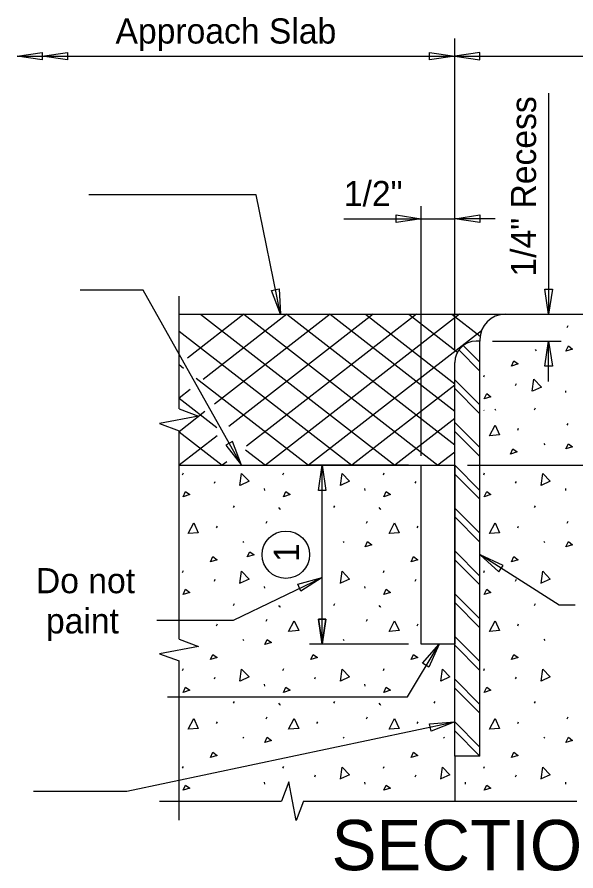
# Model space of a CAD drawing. Extents: x 2799.7 to 2896, y 515.2 to 573.9.
# Drawn here: x 2834.1 to 2841.51, y 530.53 to 541.84 of the extents above; entities that cross this region are included whole.
import ezdxf

# ---------------------------------------------------------------- set-up
doc = ezdxf.new("R2010")
doc.units = 0
for name, color, linetype in [('BR_AUTO DIMENSION', 7, 'Continuous'), ('BR_CONCRETE', 7, 'Continuous'), ('BR_DETAILS', 7, 'Continuous'), ('BR_STRUCTURAL STEEL', 7, 'Continuous'), ('BR_TABLE LINES', 7, 'Continuous'), ('BR_TEXT', 7, 'Continuous')]:
    doc.layers.add(name, color=color, linetype=linetype)

# ---------------------------------------------------------------- blocks, each defined once
blk = doc.blocks.new('B')
at = {"layer": 'BR_AUTO DIMENSION'}
blk.add_lwpolyline([(-0.2, 0.03), (0, 0), (-0.2, -0.03)], close=True, dxfattribs=at)
blk = doc.blocks.new('ARROW')
at = {"layer": 'BR_AUTO DIMENSION', "xscale": 0.625, "yscale": 0.625}
blk.add_blockref('B', (0, 0), dxfattribs=at)
blk = doc.blocks.new('DAH')
at = {"layer": 'BR_AUTO DIMENSION'}
for p in [(-0.1248, 0), (0, 0)]:
    blk.add_blockref('ARROW', p, dxfattribs=at)

msp = doc.modelspace()

# ---------------------------------------------------------------- linework, layer by layer
at = {"layer": 'BR_AUTO DIMENSION'}
for p, q in [((2839.901, 537.568), (2839.901, 541.559)), ((2834.103, 541.324), (2845.404, 541.324)), ((2841.144, 540.834), (2841.144, 537.904)), ((2837.269, 539.488), (2835.055, 539.488)), ((2837.591, 537.904), (2837.269, 539.488)), ((2839.456, 536.071), (2839.456, 539.337)), ((2839.456, 536.027), (2839.456, 539.314)), ((2839.901, 537.432), (2839.901, 539.337)), ((2838.431, 539.171), (2839.456, 539.171)), ((2838.923, 539.171), (2839.456, 539.171)), ((2839.456, 539.171), (2839.901, 539.171)), ((2840.434, 539.171), (2839.901, 539.171)), ((2835.774, 538.223), (2834.937, 538.223)), ((2837.077, 535.904), (2835.774, 538.223)), ((2840.734, 537.904), (2841.31, 537.904)), ((2840.401, 537.55), (2841.31, 537.55)), ((2841.144, 537.016), (2841.144, 537.55)), ((2839.289, 535.904), (2837.978, 535.904)), ((2838.144, 533.534), (2838.144, 535.904)), ((2840.067, 535.904), (2845.988, 535.904)), ((2841.282, 534.05), (2840.235, 534.719)), ((2836.968, 533.852), (2838.144, 534.418)), ((2841.496, 534.05), (2841.282, 534.05)), ((2835.956, 533.852), (2836.968, 533.852)), ((2839.289, 533.534), (2837.978, 533.534)), ((2839.273, 532.836), (2839.695, 533.536)), ((2836.096, 532.836), (2839.273, 532.836)), ((2835.556, 531.588), (2839.901, 532.503)), ((2834.322, 531.588), (2835.556, 531.588))]:
    msp.add_line(p, q, dxfattribs=at)
for points in [[(2839.567, 541.374), (2839.901, 541.324), (2839.567, 541.274)], [(2840.234, 541.374), (2839.901, 541.324), (2840.234, 541.274)], [(2839.123, 539.221), (2839.456, 539.171), (2839.123, 539.121)], [(2840.234, 539.121), (2839.901, 539.171), (2840.234, 539.221)], [(2837.573, 538.241), (2837.591, 537.904), (2837.475, 538.221)], [(2841.194, 538.238), (2841.144, 537.904), (2841.094, 538.238)], [(2841.094, 537.216), (2841.144, 537.55), (2841.194, 537.216)], [(2836.87, 536.17), (2837.077, 535.904), (2836.958, 536.219)], [(2838.094, 535.571), (2838.144, 535.904), (2838.194, 535.571)], [(2838.094, 535.571), (2838.144, 535.904), (2838.194, 535.571)], [(2840.54, 534.576), (2840.235, 534.719), (2840.485, 534.492)], [(2837.82, 534.327), (2838.144, 534.418), (2837.861, 534.236)], [(2838.094, 533.867), (2838.144, 533.534), (2838.194, 533.867)], [(2838.194, 533.867), (2838.144, 533.534), (2838.094, 533.867)], [(2839.473, 533.283), (2839.695, 533.536), (2839.557, 533.229)], [(2839.564, 532.48), (2839.901, 532.503), (2839.586, 532.382)]]:
    msp.add_lwpolyline(points, close=True, dxfattribs=at)
msp.add_circle((2837.663, 534.719), 0.314, dxfattribs=at)
at = {"layer": 'BR_CONCRETE'}
for p, q in [((2840.567, 537.904), (2844.821, 537.904)), ((2840.234, 537.571), (2840.234, 537.55)), ((2836.249, 535.904), (2839.456, 535.904)), ((2839.901, 532.052), (2839.901, 531.454))]:
    msp.add_line(p, q, dxfattribs=at)
msp.add_arc((2840.567, 537.571), 0.333, 90, 180, dxfattribs=at)
at = {"layer": 'BR_DETAILS'}
for p, q in [((2841.391, 537.73), (2841.402, 537.755)), ((2840.967, 537.436), (2840.978, 537.42)), ((2840.284, 537.075), (2840.295, 537.1)), ((2840.706, 536.962), (2840.717, 536.987)), ((2841.366, 536.892), (2841.368, 536.867)), ((2840.285, 536.635), (2840.288, 536.63)), ((2840.43, 536.65), (2840.441, 536.633)), ((2840.958, 536.64), (2840.969, 536.665)), ((2841.391, 536.434), (2841.402, 536.459)), ((2840.734, 536.37), (2840.745, 536.395)), ((2841.08, 536.193), (2841.092, 536.176)), ((2836.296, 535.779), (2836.307, 535.804)), ((2837.625, 535.779), (2837.636, 535.804)), ((2838.955, 535.779), (2838.966, 535.804)), ((2840.284, 535.779), (2840.295, 535.804)), ((2836.718, 535.665), (2836.729, 535.69)), ((2839.376, 535.665), (2839.388, 535.69)), ((2840.706, 535.665), (2840.717, 535.69)), ((2837.378, 535.596), (2837.38, 535.571)), ((2838.707, 535.596), (2838.71, 535.571)), ((2841.366, 535.596), (2841.368, 535.571)), ((2836.97, 535.343), (2836.981, 535.368)), ((2837.567, 535.343), (2837.578, 535.327)), ((2837.578, 535.337), (2837.589, 535.32)), ((2838.3, 535.343), (2838.311, 535.368)), ((2838.896, 535.343), (2838.907, 535.327)), ((2838.907, 535.337), (2838.919, 535.32)), ((2840.958, 535.343), (2840.969, 535.368)), ((2837.403, 535.138), (2837.414, 535.163)), ((2838.733, 535.138), (2838.744, 535.163)), ((2841.391, 535.138), (2841.402, 535.163)), ((2836.745, 535.074), (2836.757, 535.099)), ((2839.404, 535.074), (2839.415, 535.099)), ((2840.734, 535.074), (2840.745, 535.099)), ((2837.092, 534.896), (2837.103, 534.88)), ((2838.422, 534.896), (2838.433, 534.88)), ((2841.08, 534.896), (2841.092, 534.88)), ((2836.296, 534.483), (2836.307, 534.508)), ((2838.955, 534.483), (2838.966, 534.508)), ((2840.284, 534.483), (2840.295, 534.508)), ((2836.718, 534.369), (2836.729, 534.394)), ((2838.047, 534.369), (2838.058, 534.394)), ((2839.376, 534.369), (2839.388, 534.394)), ((2840.706, 534.369), (2840.717, 534.394)), ((2837.378, 534.299), (2837.38, 534.274)), ((2838.707, 534.299), (2838.71, 534.274)), ((2836.97, 534.047), (2836.981, 534.072)), ((2837.567, 534.047), (2837.578, 534.03)), ((2837.578, 534.041), (2837.589, 534.024)), ((2838.3, 534.047), (2838.311, 534.072)), ((2838.896, 534.047), (2838.907, 534.03)), ((2838.907, 534.041), (2838.919, 534.024)), ((2840.958, 534.047), (2840.969, 534.072)), ((2837.403, 533.841), (2837.414, 533.866)), ((2838.733, 533.841), (2838.744, 533.866)), ((2836.745, 533.777), (2836.757, 533.802)), ((2839.404, 533.777), (2839.415, 533.802)), ((2840.734, 533.777), (2840.745, 533.802)), ((2837.092, 533.6), (2837.103, 533.583)), ((2838.422, 533.6), (2838.433, 533.583)), ((2841.08, 533.6), (2841.092, 533.583)), ((2836.296, 533.186), (2836.307, 533.211)), ((2837.625, 533.186), (2837.636, 533.211)), ((2838.955, 533.186), (2838.966, 533.211)), ((2840.284, 533.186), (2840.295, 533.211)), ((2836.718, 533.073), (2836.729, 533.098)), ((2838.047, 533.073), (2838.058, 533.098)), ((2840.706, 533.073), (2840.717, 533.098)), ((2837.378, 533.003), (2837.38, 532.978)), ((2838.707, 533.003), (2838.71, 532.978)), ((2836.97, 532.751), (2836.981, 532.776)), ((2837.567, 532.751), (2837.578, 532.734)), ((2837.578, 532.744), (2837.589, 532.728)), ((2838.3, 532.751), (2838.311, 532.776)), ((2838.896, 532.751), (2838.907, 532.734)), ((2838.907, 532.744), (2838.919, 532.728)), ((2839.629, 532.751), (2839.64, 532.776)), ((2840.958, 532.751), (2840.969, 532.776)), ((2837.403, 532.545), (2837.414, 532.57)), ((2838.733, 532.545), (2838.744, 532.57)), ((2841.391, 532.545), (2841.402, 532.57)), ((2836.745, 532.481), (2836.757, 532.506)), ((2838.075, 532.481), (2838.086, 532.506)), ((2839.404, 532.481), (2839.415, 532.506)), ((2840.734, 532.481), (2840.745, 532.506)), ((2837.092, 532.303), (2837.103, 532.287)), ((2838.422, 532.303), (2838.433, 532.287)), ((2839.751, 532.303), (2839.762, 532.287)), ((2841.08, 532.303), (2841.092, 532.287)), ((2836.296, 531.89), (2836.307, 531.915)), ((2837.625, 531.89), (2837.636, 531.915)), ((2838.955, 531.89), (2838.966, 531.915)), ((2840.284, 531.89), (2840.295, 531.915)), ((2838.047, 531.776), (2838.058, 531.801)), ((2839.376, 531.776), (2839.388, 531.801)), ((2840.706, 531.776), (2840.717, 531.801)), ((2837.378, 531.706), (2837.38, 531.681)), ((2838.707, 531.706), (2838.71, 531.681)), ((2840.036, 531.706), (2840.039, 531.681)), ((2841.366, 531.706), (2841.368, 531.681)), ((2835.991, 531.454), (2837.607, 531.454)), ((2837.897, 531.454), (2841.515, 531.454))]:
    msp.add_line(p, q, dxfattribs=at)
for points in [[(2836.249, 536.65), (2836.249, 538.143)], [(2841.372, 537.417), (2841.405, 537.486), (2841.461, 537.444), (2841.372, 537.417)], [(2840.651, 537.218), (2840.684, 537.288), (2840.74, 537.246), (2840.651, 537.218)], [(2840.927, 536.885), (2840.949, 537.044), (2841.048, 536.941), (2840.929, 536.886)], [(2840.29, 536.784), (2840.323, 536.853), (2840.378, 536.812), (2840.29, 536.784)], [(2836.249, 536.65), (2836.506, 536.553), (2835.991, 536.457), (2836.249, 536.36)], [(2840.359, 536.295), (2840.434, 536.437), (2840.492, 536.306), (2840.362, 536.295)], [(2836.249, 533.601), (2836.249, 536.36)], [(2841.372, 536.12), (2841.405, 536.19), (2841.461, 536.148), (2841.372, 536.12)], [(2840.637, 536.053), (2840.67, 536.122), (2840.725, 536.081), (2840.637, 536.053)], [(2837.055, 535.637), (2837.077, 535.795), (2837.177, 535.693), (2837.058, 535.637)], [(2838.385, 535.637), (2838.407, 535.795), (2838.506, 535.693), (2838.387, 535.637)], [(2841.043, 535.637), (2841.065, 535.795), (2841.165, 535.693), (2841.046, 535.637)], [(2836.301, 535.488), (2836.335, 535.557), (2836.39, 535.515), (2836.301, 535.488)], [(2837.631, 535.488), (2837.664, 535.557), (2837.72, 535.515), (2837.631, 535.488)], [(2838.96, 535.488), (2838.993, 535.557), (2839.049, 535.515), (2838.96, 535.488)], [(2840.29, 535.488), (2840.323, 535.557), (2840.378, 535.515), (2840.29, 535.488)], [(2836.371, 534.999), (2836.446, 535.14), (2836.504, 535.01), (2836.374, 534.999)], [(2839.03, 534.999), (2839.104, 535.14), (2839.163, 535.01), (2839.032, 534.999)], [(2840.359, 534.999), (2840.434, 535.14), (2840.492, 535.01), (2840.362, 534.999)], [(2838.713, 534.824), (2838.746, 534.893), (2838.802, 534.852), (2838.713, 534.824)], [(2841.372, 534.824), (2841.405, 534.893), (2841.461, 534.852), (2841.372, 534.824)], [(2837.153, 534.69), (2837.187, 534.759), (2837.242, 534.718), (2837.153, 534.69)], [(2836.663, 534.626), (2836.696, 534.695), (2836.752, 534.653), (2836.663, 534.626)], [(2839.321, 534.626), (2839.355, 534.695), (2839.41, 534.653), (2839.321, 534.626)], [(2840.651, 534.626), (2840.684, 534.695), (2840.74, 534.653), (2840.651, 534.626)], [(2837.055, 534.34), (2837.077, 534.499), (2837.177, 534.396), (2837.058, 534.341)], [(2838.385, 534.34), (2838.407, 534.499), (2838.506, 534.396), (2838.387, 534.341)], [(2841.043, 534.34), (2841.065, 534.499), (2841.165, 534.396), (2841.046, 534.341)], [(2836.301, 534.191), (2836.335, 534.261), (2836.39, 534.219), (2836.301, 534.191)], [(2838.96, 534.191), (2838.993, 534.261), (2839.049, 534.219), (2838.96, 534.191)], [(2840.29, 534.191), (2840.323, 534.261), (2840.378, 534.219), (2840.29, 534.191)], [(2837.7, 533.703), (2837.775, 533.844), (2837.833, 533.714), (2837.703, 533.703)], [(2839.03, 533.703), (2839.104, 533.844), (2839.163, 533.714), (2839.032, 533.703)], [(2840.359, 533.703), (2840.434, 533.844), (2840.492, 533.714), (2840.362, 533.703)], [(2836.249, 533.601), (2836.506, 533.505), (2835.991, 533.408), (2836.249, 533.312)], [(2837.384, 533.528), (2837.417, 533.597), (2837.473, 533.555), (2837.384, 533.528)], [(2836.663, 533.329), (2836.696, 533.399), (2836.752, 533.357), (2836.663, 533.329)], [(2837.992, 533.329), (2838.025, 533.399), (2838.081, 533.357), (2837.992, 533.329)], [(2839.321, 533.329), (2839.355, 533.399), (2839.41, 533.357), (2839.321, 533.329)], [(2840.651, 533.329), (2840.684, 533.399), (2840.74, 533.357), (2840.651, 533.329)], [(2836.249, 531.202), (2836.249, 533.312)], [(2837.055, 533.044), (2837.077, 533.202), (2837.177, 533.1), (2837.058, 533.045)], [(2838.385, 533.044), (2838.407, 533.202), (2838.506, 533.1), (2838.387, 533.045)], [(2839.714, 533.044), (2839.736, 533.202), (2839.835, 533.1), (2839.717, 533.045)], [(2841.043, 533.044), (2841.065, 533.202), (2841.165, 533.1), (2841.046, 533.045)], [(2836.301, 532.895), (2836.335, 532.964), (2836.39, 532.923), (2836.301, 532.895)], [(2837.631, 532.895), (2837.664, 532.964), (2837.72, 532.923), (2837.631, 532.895)], [(2838.96, 532.895), (2838.993, 532.964), (2839.049, 532.923), (2838.96, 532.895)], [(2840.29, 532.895), (2840.323, 532.964), (2840.378, 532.923), (2840.29, 532.895)], [(2836.371, 532.406), (2836.446, 532.548), (2836.504, 532.417), (2836.374, 532.406)], [(2837.7, 532.406), (2837.775, 532.548), (2837.833, 532.417), (2837.703, 532.406)], [(2839.03, 532.406), (2839.104, 532.548), (2839.163, 532.417), (2839.032, 532.406)], [(2840.359, 532.406), (2840.434, 532.548), (2840.492, 532.417), (2840.362, 532.406)], [(2837.384, 532.231), (2837.417, 532.301), (2837.473, 532.259), (2837.384, 532.231)], [(2841.372, 532.231), (2841.405, 532.301), (2841.461, 532.259), (2841.372, 532.231)], [(2836.663, 532.033), (2836.696, 532.102), (2836.752, 532.061), (2836.663, 532.033)], [(2839.321, 532.033), (2839.355, 532.102), (2839.41, 532.061), (2839.321, 532.033)], [(2840.651, 532.033), (2840.684, 532.102), (2840.74, 532.061), (2840.651, 532.033)], [(2838.385, 531.747), (2838.407, 531.906), (2838.506, 531.803), (2838.387, 531.748)], [(2839.714, 531.747), (2839.736, 531.906), (2839.835, 531.803), (2839.717, 531.748)], [(2841.043, 531.747), (2841.065, 531.906), (2841.165, 531.803), (2841.046, 531.748)], [(2836.301, 531.599), (2836.335, 531.668), (2836.39, 531.626), (2836.301, 531.599)], [(2837.897, 531.454), (2837.8, 531.197), (2837.704, 531.712), (2837.607, 531.454)], [(2838.96, 531.599), (2838.993, 531.668), (2839.049, 531.626), (2838.96, 531.599)], [(2840.29, 531.599), (2840.323, 531.668), (2840.378, 531.626), (2840.29, 531.599)]]:
    msp.add_lwpolyline(points, dxfattribs=at)
at = {"layer": 'BR_STRUCTURAL STEEL'}
for p, q in [((2840.234, 537.55), (2840.185, 537.55)), ((2840.234, 532.052), (2840.234, 537.55)), ((2839.955, 537.432), (2840.234, 537.152)), ((2840.013, 537.492), (2840.234, 537.27)), ((2839.901, 532.052), (2839.901, 537.265)), ((2839.901, 537.038), (2840.234, 536.705)), ((2839.901, 536.92), (2840.234, 536.587)), ((2839.901, 536.471), (2840.234, 536.138)), ((2839.901, 536.353), (2840.234, 536.02)), ((2839.901, 535.904), (2840.234, 535.571)), ((2839.901, 535.786), (2840.234, 535.453)), ((2839.901, 535.337), (2840.234, 535.004)), ((2839.901, 535.219), (2840.234, 534.886)), ((2839.901, 534.77), (2840.234, 534.437)), ((2839.901, 534.652), (2840.234, 534.319)), ((2839.901, 534.203), (2840.234, 533.87)), ((2839.901, 534.086), (2840.234, 533.752)), ((2839.901, 533.637), (2840.234, 533.303)), ((2839.901, 533.519), (2840.234, 533.185)), ((2839.901, 533.07), (2840.234, 532.736)), ((2839.901, 532.952), (2840.234, 532.618)), ((2839.901, 532.503), (2840.234, 532.169)), ((2839.901, 532.385), (2840.234, 532.052)), ((2840.234, 532.052), (2839.901, 532.052))]:
    msp.add_line(p, q, dxfattribs=at)
msp.add_arc((2840.185, 537.265), 0.284, 90, 180, dxfattribs=at)
at = {"layer": 'BR_TABLE LINES'}
for p, q in [((2836.249, 537.904), (2840.567, 537.904)), ((2837.106, 537.904), (2836.359, 537.323)), ((2836.534, 537.904), (2839.106, 535.904)), ((2837.677, 537.904), (2836.567, 537.041)), ((2838.249, 537.904), (2836.718, 536.713)), ((2838.82, 537.904), (2836.91, 536.419)), ((2837.106, 537.904), (2839.677, 535.904)), ((2839.392, 537.904), (2837.144, 536.156)), ((2839.963, 537.904), (2837.392, 535.904)), ((2837.677, 537.904), (2839.901, 536.175)), ((2838.249, 537.904), (2839.901, 536.62)), ((2838.719, 537.904), (2839.901, 536.985)), ((2839.291, 537.904), (2839.936, 537.402)), ((2839.862, 537.904), (2840.237, 537.613)), ((2836.249, 537.682), (2838.535, 535.904)), ((2840.255, 537.686), (2837.963, 535.904)), ((2836.249, 537.238), (2836.308, 537.191)), ((2836.476, 537.06), (2837.963, 535.904)), ((2836.398, 536.909), (2836.249, 536.793)), ((2839.901, 536.967), (2838.535, 535.904)), ((2836.249, 536.793), (2836.747, 536.406)), ((2836.591, 536.615), (2836.249, 536.349)), ((2839.901, 536.522), (2839.106, 535.904)), ((2836.249, 536.349), (2836.82, 535.904)), ((2836.752, 536.295), (2836.249, 535.904)), ((2837.13, 536.107), (2837.392, 535.904)), ((2839.901, 536.078), (2839.677, 535.904)), ((2836.881, 535.951), (2836.82, 535.904))]:
    msp.add_line(p, q, dxfattribs=at)
msp.add_lwpolyline([(2839.456, 535.904), (2839.901, 535.904), (2839.901, 533.534), (2839.456, 533.534)], close=True, dxfattribs=at)

# ---------------------------------------------------------------- block references
at = {"layer": 'BR_AUTO DIMENSION', "xscale": 2.6668000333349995, "yscale": 2.6668000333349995, "rotation": 180}
msp.add_blockref('DAH', (2834.103, 541.324), dxfattribs=at)

# ---------------------------------------------------------------- texts
at = {"layer": 'BR_AUTO DIMENSION'}
msp.add_text('1/4" Recess', height=0.33335, rotation=90, dxfattribs=at).set_placement((2840.977, 538.404))
msp.add_text('1/2"', height=0.3334, dxfattribs=at).set_placement((2838.431, 539.337))
at = {"layer": 'BR_TEXT'}
for s, height, p in [('Approach Slab', 0.33332, (2835.407, 541.491)), ('Do not', 0.3333, (2834.353, 534.209)), ('paint', 0.3333, (2834.486, 533.676)), ('SECTION C-C', 0.66673, (2838.269, 530.539))]:
    msp.add_text(s, height=height, dxfattribs=at).set_placement(p)
msp.add_text('1', height=0.333, rotation=90, dxfattribs=at).set_placement((2837.837, 534.622))

doc.saveas('drawing.dxf')
